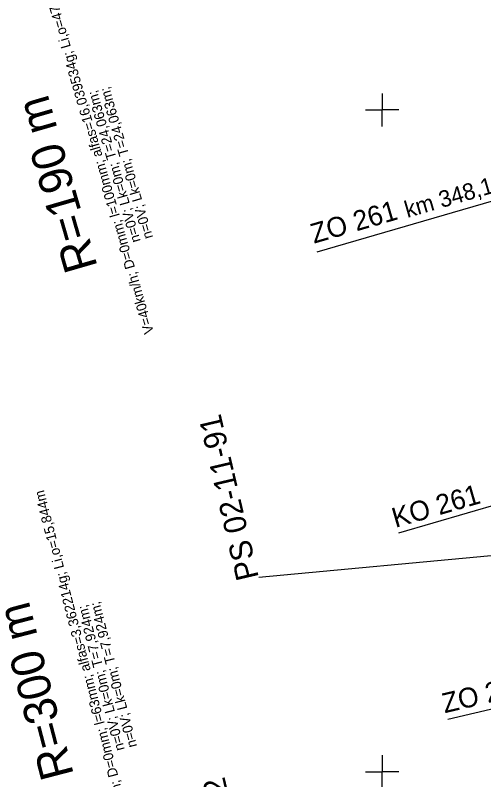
# Model space of a CAD drawing. Extents: x -821029 to -820632, y -1070881 to -1069931.
# Drawn here: x -820877.7 to -820842.3, y -1070400.6 to -1070342.9 of the extents above; entities that cross this region are included whole.
import ezdxf

# ---------------------------------------------------------------- set-up
doc = ezdxf.new("R2010")
doc.units = 0
for name, color, linetype in [('_PS_SO_číslo', 7, 'Continuous'), ('Sit', 7, 'Continuous'), ('SO-11-10-01', 7, 'Continuous')]:
    doc.layers.add(name, color=color, linetype=linetype)

msp = doc.modelspace()

# ---------------------------------------------------------------- linework, layer by layer
at = {"layer": '_PS_SO_číslo'}
msp.add_line((-820825.628, -1070382.193), (-820859.303, -1070385.322), dxfattribs=at)
at = {"layer": 'Sit'}
for p, q in [((-820850, -1070348.75), (-820850, -1070350)), ((-820851.25, -1070350), (-820850, -1070350)), ((-820848.75, -1070350), (-820850, -1070350)), ((-820850, -1070351.25), (-820850, -1070350)), ((-820850, -1070398.75), (-820850, -1070400)), ((-820851.25, -1070400), (-820850, -1070400)), ((-820848.75, -1070400), (-820850, -1070400)), ((-820850, -1070401.25), (-820850, -1070400))]:
    msp.add_line(p, q, dxfattribs=at)
at = {"layer": 'SO-11-10-01'}
for p, q in [((-820854.904, -1070360.722), (-820830.896, -1070353.751)), ((-820848.74, -1070381.942), (-820824.726, -1070374.992)), ((-820845.048, -1070396.034), (-820820.711, -1070390.317))]:
    msp.add_line(p, q, dxfattribs=at)

# ---------------------------------------------------------------- texts
at = {"layer": '_PS_SO_číslo'}
for s, p in [('PS 02-11-91', (-820859.303, -1070385.322)), ('SO 11-72-01.12', (-820858.235, -1070416.07))]:
    msp.add_text(s, height=1.7, rotation=103.1578, dxfattribs=at).set_placement(p)
at = {"layer": 'SO-11-10-01'}
for s, height, rotation, p in [('V=40km/h; D=0mm; l=100mm; alfas=16,039534g; Li,o=47,87m', 0.75, 106.19376, (-820867.231, -1070366.806)), ('n=0V; Lk=0m; T=24,063m;', 0.75, 106.19376, (-820867.295, -1070359.626)), ('R=190 m', 2.5, 106.19376, (-820871.471, -1070361.844)), ('n=0V; Lk=0m; T=24,063m;', 0.75, 106.19376, (-820868.227, -1070359.897)), ('km 348,139 172', 1.25, 16.19212, (-820848.096, -1070358.166)), ('ZO 261 ', 1.5, 16.19212, (-820855.146, -1070360.11)), ('KO 261 ', 1.5, 16.14159, (-820849.002, -1070381.585)), ('V=40km/h; D=0mm; l=63mm; alfas=3,362214g; Li,o=15,844m', 0.75, 104.57523, (-820868.636, -1070405.248)), ('R=300 m', 2.5, 104.57523, (-820873.267, -1070400.23)), ('n=0V; Lk=0m; T=7,924m;', 0.75, 104.57523, (-820869.437, -1070398.313)), ('n=0V; Lk=0m; T=7,924m;', 0.75, 104.57523, (-820868.497, -1070398.069)), ('ZO 261 ', 1.5, 13.22041, (-820845.277, -1070395.586))]:
    msp.add_text(s, height=height, rotation=rotation, dxfattribs=at).set_placement(p)

doc.saveas('drawing.dxf')
